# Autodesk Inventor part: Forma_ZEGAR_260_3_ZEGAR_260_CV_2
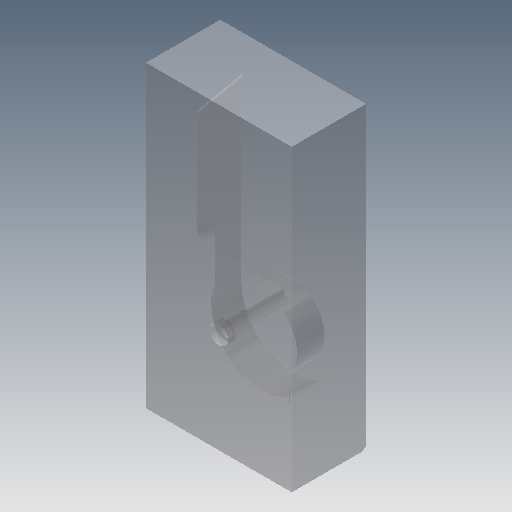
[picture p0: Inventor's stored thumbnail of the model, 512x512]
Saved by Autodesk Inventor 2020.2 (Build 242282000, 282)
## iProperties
Created: 2015-01
Part Number: Forma_ZEGAR_260_3_ZEGAR_260_CV_2
Material: Ogólny
Document SubType Name: Modeling
Designer: F.Stasiak
Density: 1 g/cm^3
Appearance: Domyślna
Catalog Web Link: www.expertbooks.pl
Manager: www.cadconsulting.pl
Company: Fabian Stasiak CAD Consulting
Author: F.Stasiak
Subject: Zbiór ćwiczeń. Autodesk Inventor 2020. Kurs Professional
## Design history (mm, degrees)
node "Forma_ZEGAR_260_3_ZEGAR_260_CV_Base"
feature "Rzeźbienie3"
feature "Bryła1::Forma_ZEGAR_260_3_ZEGAR_260_CV_Base"
tag "Bryła wyprowadzona1"
node "Bryła1"
feature "Forma_ZEGAR_260_3_ZEGAR_260_CV_Base_Bodies"
feature "Powierzchnia3"
body "Srf3"
